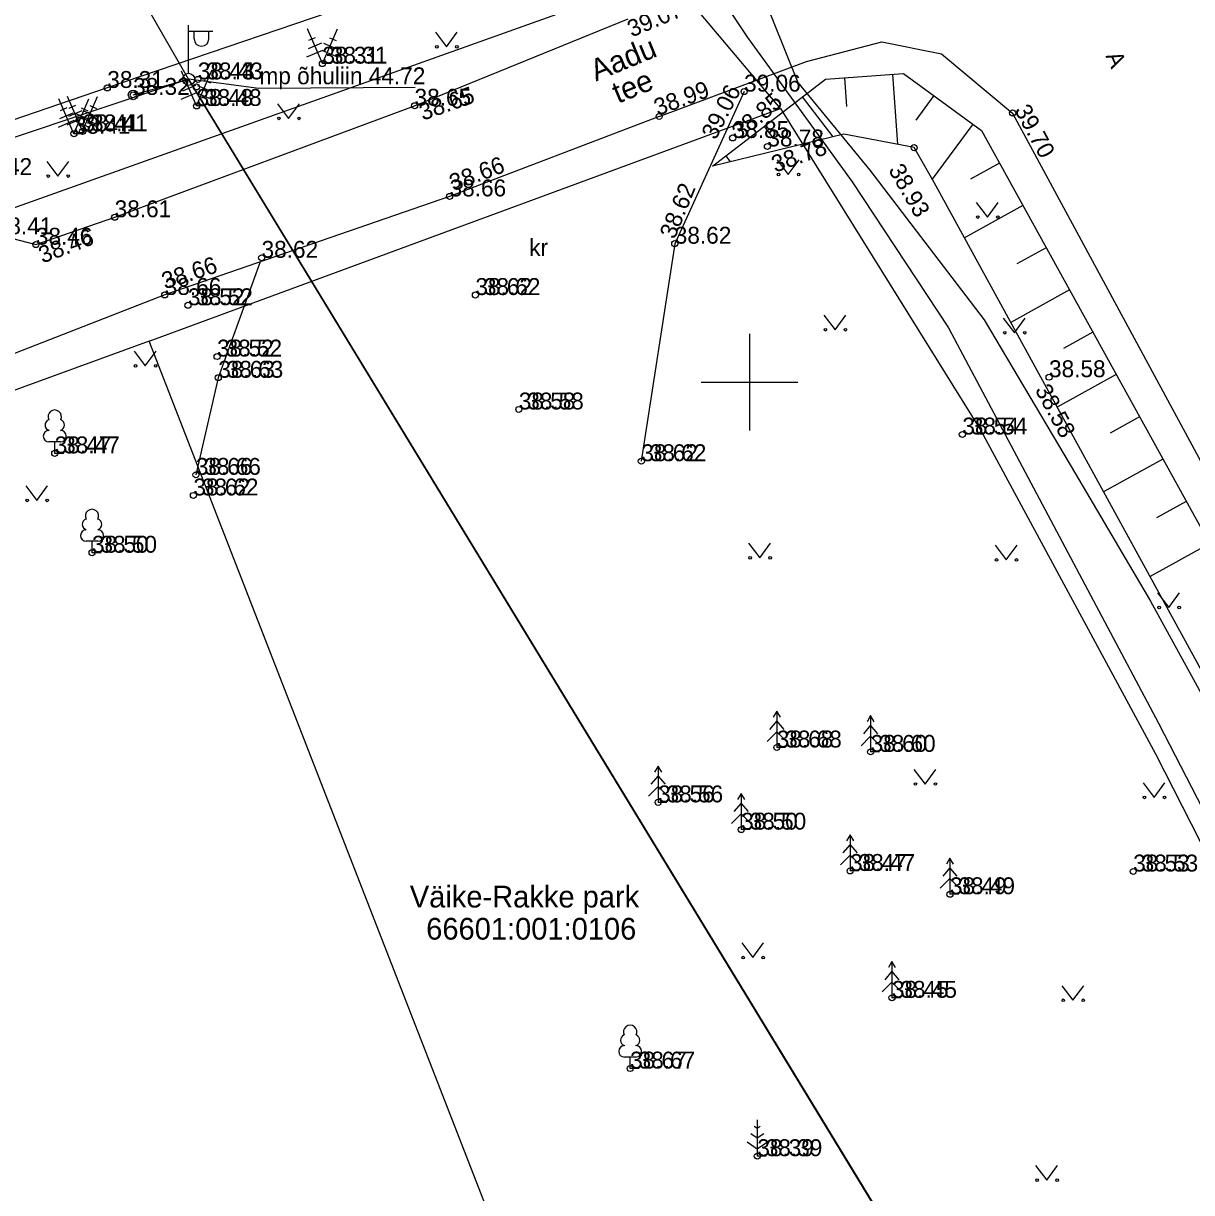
# Model space of a CAD drawing. Extents: x 627548 to 628052, y 6467984 to 6468802.
# Drawn here: x 627769.93 to 627818.31, y 6468416.43 to 6468464.86 of the extents above; entities that cross this region are included whole.
import ezdxf

# ---------------------------------------------------------------- set-up
doc = ezdxf.new("R2010")
doc.units = 0
for name, color, linetype in [('ABIJOONIS', 7, 'Continuous'), ('AED', 7, 'Continuous'), ('HALJASTUS', 7, 'Continuous'), ('KORGUS-EH2000', 7, 'Continuous'), ('MOOTKORG-EH2000', 7, 'Continuous'), ('MOOTMPUNKT', 7, 'Continuous'), ('MPOHULIIN', 7, 'Continuous'), ('PIIR', 7, 'Continuous'), ('POST', 7, 'Continuous'), ('PUU', 7, 'Continuous'), ('RELJEEF', 7, 'Continuous'), ('SIOHULIIN', 7, 'Continuous'), ('SITRASS', 7, 'Continuous'), ('TEE', 7, 'Continuous'), ('VORK', 7, 'Continuous')]:
    doc.layers.add(name, color=color, linetype=linetype)

msp = doc.modelspace()

# ---------------------------------------------------------------- linework, layer by layer
at = {"layer": 'ABIJOONIS'}
msp.add_lwpolyline([(627786.149, 6468462.211), (627779.68, 6468462.167), (627776.772, 6468462.547)], dxfattribs=at)
at = {"layer": 'AED'}
msp.add_lwpolyline([(627793.589, 6468469.234), (627785.422, 6468466.301), (627773.403, 6468462.19), (627765.44, 6468459.471)], dxfattribs=at)
at = {"layer": 'HALJASTUS'}
for p, q in [((627786.991, 6468464.496), (627787.455, 6468463.89)), ((627787.455, 6468463.89), (627787.9, 6468464.496)), ((627780.452, 6468461.538), (627780.915, 6468460.931)), ((627780.915, 6468460.931), (627781.361, 6468461.538)), ((627770.898, 6468459.148), (627771.361, 6468458.541)), ((627771.361, 6468458.541), (627771.807, 6468459.148)), ((627801.146, 6468459.215), (627801.609, 6468458.609)), ((627801.609, 6468458.609), (627802.055, 6468459.215)), ((627809.389, 6468457.45), (627809.853, 6468456.843)), ((627809.853, 6468456.843), (627810.298, 6468457.45)), ((627803.081, 6468452.783), (627803.544, 6468452.176)), ((627803.544, 6468452.176), (627803.99, 6468452.783)), ((627810.508, 6468452.659), (627810.971, 6468452.052)), ((627810.971, 6468452.052), (627811.417, 6468452.659)), ((627774.516, 6468451.29), (627774.979, 6468450.683)), ((627774.979, 6468450.683), (627775.424, 6468451.29)), ((627770.023, 6468445.714), (627770.486, 6468445.107)), ((627770.486, 6468445.107), (627770.932, 6468445.714)), ((627799.963, 6468443.33), (627800.426, 6468442.723)), ((627800.426, 6468442.723), (627800.872, 6468443.33)), ((627810.171, 6468443.244), (627810.635, 6468442.637)), ((627810.635, 6468442.637), (627811.08, 6468443.244)), ((627816.904, 6468441.278), (627817.367, 6468440.671)), ((627817.367, 6468440.671), (627817.813, 6468441.278)), ((627806.808, 6468433.963), (627807.271, 6468433.357)), ((627807.271, 6468433.357), (627807.717, 6468433.963)), ((627816.299, 6468433.41), (627816.762, 6468432.803)), ((627816.762, 6468432.803), (627817.208, 6468433.41)), ((627799.678, 6468426.772), (627800.142, 6468426.165)), ((627800.142, 6468426.165), (627800.587, 6468426.772)), ((627812.935, 6468425.003), (627813.398, 6468424.397)), ((627813.398, 6468424.397), (627813.844, 6468425.003)), ((627811.848, 6468417.554), (627812.311, 6468416.948)), ((627812.311, 6468416.948), (627812.757, 6468417.554))]:
    msp.add_line(p, q, dxfattribs=at)
for centre in [(627787.054, 6468463.89), (627787.882, 6468463.89), (627780.514, 6468460.931), (627781.343, 6468460.931), (627770.96, 6468458.541), (627771.789, 6468458.541), (627801.208, 6468458.609), (627802.037, 6468458.609), (627809.452, 6468456.843), (627810.28, 6468456.843), (627803.143, 6468452.176), (627803.972, 6468452.176), (627810.57, 6468452.052), (627811.399, 6468452.052), (627774.578, 6468450.683), (627775.407, 6468450.683), (627770.085, 6468445.107), (627770.914, 6468445.107), (627800.025, 6468442.723), (627800.854, 6468442.723), (627810.234, 6468442.637), (627811.063, 6468442.637), (627816.966, 6468440.671), (627817.795, 6468440.671), (627806.87, 6468433.357), (627807.699, 6468433.357), (627816.361, 6468432.803), (627817.19, 6468432.803), (627799.741, 6468426.165), (627800.57, 6468426.165), (627812.997, 6468424.397), (627813.826, 6468424.397), (627811.91, 6468416.948), (627812.739, 6468416.948)]:
    msp.add_circle(centre, 0.055, dxfattribs=at)
at = {"layer": 'KORGUS-EH2000'}
for centre in [(627810.9, 6468461.157), (627796.26, 6468461.007), (627806.82, 6468459.717)]:
    msp.add_circle(centre, 0.125, dxfattribs=at)
at = {"layer": 'MOOTMPUNKT'}
for centre in [(627782.313, 6468463.197), (627777.155, 6468462.545), (627773.403, 6468462.19), (627777.095, 6468462.233), (627774.474, 6468461.904), (627799.778, 6468462.039), (627777.103, 6468461.445), (627786.129, 6468461.455), (627772.022, 6468460.293), (627772.383, 6468460.393), (627799.303, 6468460.118), (627800.741, 6468459.766), (627787.58, 6468457.698), (627773.709, 6468456.834), (627770.445, 6468455.699), (627796.906, 6468455.739), (627779.793, 6468455.154), (627775.784, 6468453.617), (627788.65, 6468453.613), (627776.742, 6468453.189), (627777.951, 6468451.064), (627778, 6468450.186), (627812.406, 6468450.208), (627790.447, 6468448.872), (627808.816, 6468447.835), (627771.227, 6468447.054), (627795.521, 6468446.729), (627777.072, 6468446.164), (627776.971, 6468445.31), (627772.771, 6468442.938), (627801.131, 6468434.87), (627805.019, 6468434.689), (627796.218, 6468432.597), (627799.657, 6468431.467), (627804.168, 6468429.756), (627815.891, 6468429.733), (627808.304, 6468428.791), (627805.901, 6468424.5), (627795.058, 6468421.57), (627800.325, 6468417.941)]:
    msp.add_circle(centre, 0.125, dxfattribs=at)
at = {"layer": 'MPOHULIIN'}
msp.add_line((627808.24, 6468410.853), (627776.772, 6468462.547), dxfattribs=at)
for points in [[(627776.772, 6468462.547), (627769.965, 6468474.421)], [(627776.772, 6468462.547), (627750.093, 6468453.636)]]:
    msp.add_lwpolyline(points, dxfattribs=at)
at = {"layer": 'PIIR'}
for p, q in [((627796.61, 6468466.88), (627730.27, 6468443.22)), ((627801.28, 6468461.34), (627796.61, 6468466.88)), ((627775.14, 6468451.7), (627801.28, 6468461.34)), ((627801.28, 6468461.34), (627809.58, 6468448)), ((627775.14, 6468451.7), (627729.69, 6468435.15)), ((627802.03, 6468382.61), (627775.14, 6468451.7)), ((627809.58, 6468448), (627816.81, 6468434.6)), ((627816.81, 6468434.6), (627826.02, 6468416.53))]:
    msp.add_line(p, q, dxfattribs=at)
at = {"layer": 'POST'}
for p, q in [((627776.772, 6468462.797), (627776.772, 6468464.797)), ((627776.772, 6468464.547), (627777.772, 6468464.547)), ((627776.999, 6468464.226), (627776.999, 6468464.547)), ((627777.611, 6468464.226), (627777.611, 6468464.547))]:
    msp.add_line(p, q, dxfattribs=at)
msp.add_lwpolyline([(627774.474, 6468461.904), (627776.772, 6468462.547)], dxfattribs=at)
for centre, radius in [((627776.772, 6468462.547), 0.25), ((627776.772, 6468462.547), 0.0234), ((627774.474, 6468461.904), 0.2)]:
    msp.add_circle(centre, radius, dxfattribs=at)
msp.add_arc((627777.305, 6468464.226), 0.306, 180, 0, dxfattribs=at)
at = {"layer": 'PUU'}
for p, q in [((627782.313, 6468463.197), (627781.692, 6468464.644)), ((627782.313, 6468463.197), (627782.934, 6468464.644)), ((627782.017, 6468464.267), (627781.741, 6468464.149)), ((627782.609, 6468464.267), (627782.885, 6468464.149)), ((627782.313, 6468463.741), (627781.656, 6468463.459)), ((627782.273, 6468464.05), (627781.722, 6468463.814)), ((627782.313, 6468463.741), (627782.97, 6468463.459)), ((627782.353, 6468464.05), (627782.904, 6468463.814)), ((627782.673, 6468463.197), (627782.313, 6468463.197)), ((627777.103, 6468461.445), (627776.482, 6468462.892)), ((627777.103, 6468461.445), (627777.724, 6468462.892)), ((627777.063, 6468462.298), (627776.512, 6468462.062)), ((627776.807, 6468462.515), (627776.531, 6468462.397)), ((627777.143, 6468462.298), (627777.694, 6468462.062)), ((627777.399, 6468462.515), (627777.675, 6468462.397)), ((627772.022, 6468460.293), (627771.401, 6468461.74)), ((627772.383, 6468460.393), (627771.762, 6468461.84)), ((627772.022, 6468460.293), (627772.643, 6468461.74)), ((627772.383, 6468460.393), (627773.004, 6468461.84)), ((627777.103, 6468461.989), (627776.446, 6468461.707)), ((627777.103, 6468461.989), (627777.76, 6468461.707)), ((627771.726, 6468461.363), (627771.45, 6468461.245)), ((627772.343, 6468461.246), (627771.792, 6468461.01)), ((627772.087, 6468461.463), (627771.811, 6468461.345)), ((627772.318, 6468461.363), (627772.594, 6468461.245)), ((627772.423, 6468461.246), (627772.974, 6468461.01)), ((627772.679, 6468461.463), (627772.955, 6468461.345)), ((627777.463, 6468461.445), (627777.103, 6468461.445)), ((627772.022, 6468460.837), (627771.365, 6468460.555)), ((627771.982, 6468461.146), (627771.431, 6468460.91)), ((627772.383, 6468460.937), (627771.726, 6468460.655)), ((627772.022, 6468460.837), (627772.679, 6468460.555)), ((627772.062, 6468461.146), (627772.613, 6468460.91)), ((627772.383, 6468460.937), (627773.04, 6468460.655)), ((627772.382, 6468460.293), (627772.022, 6468460.293)), ((627772.743, 6468460.393), (627772.383, 6468460.393)), ((627771.467, 6468447.529), (627770.987, 6468447.529)), ((627771.227, 6468447.054), (627771.227, 6468447.529)), ((627771.607, 6468447.054), (627771.227, 6468447.054)), ((627773.011, 6468443.413), (627772.531, 6468443.413)), ((627772.771, 6468442.938), (627772.771, 6468443.413)), ((627773.151, 6468442.938), (627772.771, 6468442.938)), ((627801.131, 6468436.37), (627800.981, 6468436.12)), ((627801.281, 6468436.12), (627801.131, 6468436.37)), ((627801.131, 6468436.37), (627801.131, 6468434.87)), ((627805.019, 6468436.189), (627804.869, 6468435.939)), ((627805.169, 6468435.939), (627805.019, 6468436.189)), ((627805.019, 6468436.189), (627805.019, 6468434.689)), ((627801.131, 6468435.97), (627800.831, 6468435.62)), ((627801.431, 6468435.62), (627801.131, 6468435.97)), ((627805.019, 6468435.789), (627804.719, 6468435.439)), ((627805.319, 6468435.439), (627805.019, 6468435.789)), ((627801.131, 6468435.52), (627800.731, 6468435.12)), ((627801.531, 6468435.12), (627801.131, 6468435.52)), ((627805.019, 6468435.339), (627804.619, 6468434.939)), ((627805.419, 6468434.939), (627805.019, 6468435.339)), ((627801.491, 6468434.87), (627801.131, 6468434.87)), ((627805.379, 6468434.689), (627805.019, 6468434.689)), ((627796.218, 6468434.097), (627796.068, 6468433.847)), ((627796.368, 6468433.847), (627796.218, 6468434.097)), ((627796.218, 6468434.097), (627796.218, 6468432.597)), ((627796.218, 6468433.697), (627795.918, 6468433.347)), ((627796.518, 6468433.347), (627796.218, 6468433.697)), ((627796.218, 6468433.247), (627795.818, 6468432.847)), ((627796.618, 6468432.847), (627796.218, 6468433.247)), ((627799.657, 6468432.967), (627799.507, 6468432.717)), ((627799.807, 6468432.717), (627799.657, 6468432.967)), ((627799.657, 6468432.967), (627799.657, 6468431.467)), ((627796.578, 6468432.597), (627796.218, 6468432.597)), ((627799.657, 6468432.567), (627799.357, 6468432.217)), ((627799.957, 6468432.217), (627799.657, 6468432.567)), ((627799.657, 6468432.117), (627799.257, 6468431.717)), ((627800.057, 6468431.717), (627799.657, 6468432.117)), ((627800.017, 6468431.467), (627799.657, 6468431.467)), ((627804.168, 6468431.256), (627804.018, 6468431.006)), ((627804.318, 6468431.006), (627804.168, 6468431.256)), ((627804.168, 6468431.256), (627804.168, 6468429.756)), ((627804.168, 6468430.856), (627803.868, 6468430.506)), ((627804.468, 6468430.506), (627804.168, 6468430.856)), ((627804.168, 6468430.406), (627803.768, 6468430.006)), ((627804.568, 6468430.006), (627804.168, 6468430.406)), ((627808.304, 6468430.291), (627808.154, 6468430.041)), ((627808.454, 6468430.041), (627808.304, 6468430.291)), ((627808.304, 6468430.291), (627808.304, 6468428.791)), ((627804.528, 6468429.756), (627804.168, 6468429.756)), ((627808.304, 6468429.891), (627808.004, 6468429.541)), ((627808.604, 6468429.541), (627808.304, 6468429.891)), ((627808.304, 6468429.441), (627807.904, 6468429.041)), ((627808.704, 6468429.041), (627808.304, 6468429.441)), ((627808.664, 6468428.791), (627808.304, 6468428.791)), ((627805.901, 6468426), (627805.751, 6468425.75)), ((627806.051, 6468425.75), (627805.901, 6468426)), ((627805.901, 6468426), (627805.901, 6468424.5)), ((627805.901, 6468425.6), (627805.601, 6468425.25)), ((627806.201, 6468425.25), (627805.901, 6468425.6)), ((627805.901, 6468425.15), (627805.501, 6468424.75)), ((627806.301, 6468424.75), (627805.901, 6468425.15)), ((627806.261, 6468424.5), (627805.901, 6468424.5)), ((627795.298, 6468422.045), (627794.818, 6468422.045)), ((627795.058, 6468421.57), (627795.058, 6468422.045)), ((627795.438, 6468421.57), (627795.058, 6468421.57)), ((627800.325, 6468419.091), (627800.201, 6468419.174)), ((627800.325, 6468419.441), (627800.325, 6468417.941)), ((627800.449, 6468419.174), (627800.325, 6468419.091)), ((627800.325, 6468418.691), (627800.058, 6468418.869)), ((627800.592, 6468418.869), (627800.325, 6468418.691)), ((627799.901, 6468418.53), (627800.325, 6468418.248)), ((627800.325, 6468418.248), (627800.749, 6468418.53)), ((627800.685, 6468417.941), (627800.325, 6468417.941))]:
    msp.add_line(p, q, dxfattribs=at)
for centre, radius, start, end in [((627771.227, 6468448.574), 0.277, 332.5799, 207.4201), ((627771.057, 6468448.227), 0.233, 109.0217, 253.1415), ((627771.397, 6468448.227), 0.233, 286.8508, 70.9859), ((627770.99, 6468447.766), 0.238, 90.0016, 269.3953), ((627771.464, 6468447.766), 0.238, 270.6047, 89.9984), ((627772.601, 6468444.111), 0.233, 109.0217, 253.1415), ((627772.771, 6468444.458), 0.277, 332.5799, 207.4201), ((627772.941, 6468444.111), 0.233, 286.8508, 70.9859), ((627772.534, 6468443.65), 0.238, 90.0016, 269.3953), ((627773.008, 6468443.65), 0.238, 270.6047, 89.9984), ((627794.888, 6468422.743), 0.233, 109.0217, 253.1415), ((627795.058, 6468423.09), 0.277, 332.5799, 207.4201), ((627795.228, 6468422.743), 0.233, 286.8508, 70.9859), ((627794.821, 6468422.282), 0.238, 90.0016, 269.3953), ((627795.295, 6468422.282), 0.238, 270.6047, 89.9984)]:
    msp.add_arc(centre, radius, start, end, dxfattribs=at)
at = {"layer": 'RELJEEF'}
for p, q in [((627805.93, 6468462.755), (627806.136, 6468459.848)), ((627803.935, 6468462.614), (627804.02, 6468461.423)), ((627802.189, 6468461.817), (627803.459, 6468460.164)), ((627807.631, 6468461.876), (627806.889, 6468460.861)), ((627800.603, 6468460.598), (627800.968, 6468460.124)), ((627809.245, 6468460.695), (627807.573, 6468458.409)), ((627799.017, 6468459.38), (627799.206, 6468459.134)), ((627810.359, 6468459.073), (627809.151, 6468458.406)), ((627811.326, 6468457.322), (627808.904, 6468455.985)), ((627812.292, 6468455.572), (627811.078, 6468454.901)), ((627813.259, 6468453.821), (627810.825, 6468452.477)), ((627814.226, 6468452.07), (627813.006, 6468451.396)), ((627815.192, 6468450.319), (627812.747, 6468448.969)), ((627816.159, 6468448.568), (627814.933, 6468447.891)), ((627817.126, 6468446.817), (627814.668, 6468445.46)), ((627818.092, 6468445.066), (627816.861, 6468444.386)), ((627819.059, 6468443.315), (627816.59, 6468441.952))]:
    msp.add_line(p, q, dxfattribs=at)
for points in [[(627798.462, 6468458.953), (627803.154, 6468462.558), (627806.385, 6468462.787), (627809.612, 6468460.426), (627831.39, 6468420.981), (627849.758, 6468382.754), (627863.845, 6468351.725), (627866.293, 6468345.533)], [(627863.023, 6468347.157), (627861.127, 6468351.404), (627847.089, 6468382.059), (627829.031, 6468419.236), (627807.647, 6468458.279), (627806.821, 6468459.718), (627803.902, 6468460.271), (627798.462, 6468458.953)]]:
    msp.add_lwpolyline(points, dxfattribs=at)
at = {"layer": 'SIOHULIIN'}
for points in [[(627776.772, 6468462.547), (627750.093, 6468453.636)], [(627776.772, 6468462.547), (627808.24, 6468410.853)]]:
    msp.add_lwpolyline(points, dxfattribs=at)
at = {"layer": 'SITRASS'}
for points in [[(627757.217, 6468532.631), (627766.085, 6468521.026), (627772.396, 6468510.946), (627774.395, 6468507.251), (627778.965, 6468498.694), (627784.571, 6468489.044), (627791.177, 6468479.022), (627796.223, 6468473.32), (627799.931, 6468467.58), (627802.003, 6468462.412), (627804.987, 6468458.791), (627809.717, 6468452.583), (627813.499, 6468446.21), (627816.609, 6468440.925), (627819.703, 6468435.299), (627820.118, 6468434.673)], [(627757.269, 6468529.067), (627768.1, 6468513.354), (627774.946, 6468502.943), (627783.7, 6468488.286), (627791.516, 6468476.471), (627794.222, 6468472.86), (627799.922, 6468464.28), (627804.258, 6468458.3), (627808.24, 6468452.254), (627816.937, 6468435.872), (627827.445, 6468415.491), (627836.355, 6468397.304), (627844.956, 6468379.511), (627852.286, 6468362.282), (627856.189, 6468352.574), (627857.741, 6468350.531), (627858.742, 6468350.866)]]:
    msp.add_lwpolyline(points, dxfattribs=at)
at = {"layer": 'TEE'}
for points in [[(627765.165, 6468459.007), (627766.223, 6468457.303), (627768.784, 6468456.128), (627770.445, 6468455.699), (627773.709, 6468456.834), (627786.129, 6468461.455), (627794.971, 6468465.055)], [(627796.263, 6468461.011), (627802.362, 6468463.279), (627805.478, 6468464.096), (627807.948, 6468463.607), (627810.898, 6468461.152), (627832.359, 6468421.429), (627850.995, 6468383.192), (627865.917, 6468348.418)], [(627799.778, 6468462.039), (627796.906, 6468455.739), (627795.521, 6468446.729)], [(627796.263, 6468461.011), (627787.58, 6468457.698), (627775.784, 6468453.617), (627755.708, 6468445.797), (627743.362, 6468441.806), (627728.433, 6468436.983), (627717.465, 6468433.665), (627699.12, 6468428.233), (627696.098, 6468427.452), (627683.485, 6468423.1), (627674.185, 6468419.981), (627673.482, 6468419.039), (627673.355, 6468417.806)], [(627779.731, 6468454.983), (627778, 6468450.186), (627777.072, 6468446.164)]]:
    msp.add_lwpolyline(points, dxfattribs=at)
at = {"layer": 'VORK'}
for p, q in [((627800, 6468452), (627800, 6468448)), ((627798, 6468450), (627802, 6468450))]:
    msp.add_line(p, q, dxfattribs=at)

# ---------------------------------------------------------------- texts
at = {"layer": 'ABIJOONIS'}
msp.add_text('mp õhuliin 44.72', height=0.7, dxfattribs=at).set_placement((627779.707, 6468462.343))
at = {"layer": 'KORGUS-EH2000'}
for s, rotation, p in [(' 39.07', 22.7456, (627794.887, 6468464.179)), ('38.65', 19.5762, (627786.473, 6468460.829)), (' 38.99', 20.3984, (627795.962, 6468460.939)), ('39.06', 62.977, (627798.6, 6468460.005)), ('38.85', 40.2999, (627799.639, 6468460.007)), (' 39.70', 298.3809, (627810.833, 6468461.504)), ('38.78', 19.9158, (627801.066, 6468458.677)), ('38.66', 20.4877, (627787.73, 6468457.905)), (' 38.93', 299.8562, (627805.607, 6468459.021)), ('38.62', 67.7949, (627796.9, 6468455.892)), ('38.46', 20.5618, (627770.719, 6468454.915)), ('38.66', 18.0281, (627775.794, 6468453.841)), ('38.58', 298.3103, (627811.807, 6468449.688))]:
    msp.add_text(s, height=0.7, rotation=rotation, dxfattribs=at).set_placement(p)
for s, p in [('38.31', (627782.663, 6468463.197)), ('38.43', (627777.505, 6468462.545)), ('38.48', (627777.453, 6468461.445)), ('38.41', (627772.733, 6468460.393)), ('38.42', (627767.947, 6468458.583)), ('38.62', (627789, 6468453.613)), ('38.52', (627777.092, 6468453.189)), ('38.52', (627778.301, 6468451.064)), ('38.63', (627778.35, 6468450.186)), ('38.58', (627790.797, 6468448.872)), ('38.54', (627809.166, 6468447.835)), ('38.47', (627771.577, 6468447.054)), ('38.62', (627795.871, 6468446.729)), ('38.66', (627777.422, 6468446.164)), ('38.62', (627777.321, 6468445.31)), ('38.50', (627773.121, 6468442.938)), ('38.68', (627801.481, 6468434.87)), ('38.60', (627805.369, 6468434.689)), ('38.56', (627796.568, 6468432.597)), ('38.50', (627800.007, 6468431.467)), ('38.47', (627804.518, 6468429.756)), ('38.53', (627816.241, 6468429.733)), ('38.49', (627808.654, 6468428.791)), ('38.45', (627806.251, 6468424.5)), ('38.67', (627795.408, 6468421.57)), ('38.39', (627800.675, 6468417.941))]:
    msp.add_text(s, height=0.7, dxfattribs=at).set_placement(p)
at = {"layer": 'MOOTKORG-EH2000'}
for s, p in [('38.31', (627782.313, 6468463.197)), ('38.44', (627777.152, 6468462.545)), ('38.43', (627777.155, 6468462.545)), ('38.31', (627773.403, 6468462.19)), ('39.06', (627799.778, 6468462.039)), ('38.32', (627774.474, 6468461.904)), ('38.48', (627777.103, 6468461.445)), ('38.65', (627786.129, 6468461.455)), ('38.41', (627772.022, 6468460.293)), ('38.41', (627772.383, 6468460.393)), ('38.85', (627799.303, 6468460.118)), ('38.78', (627800.741, 6468459.766)), ('38.66', (627787.58, 6468457.698)), ('38.61', (627773.709, 6468456.834)), ('38.41', (627768.784, 6468456.128)), ('38.46', (627770.445, 6468455.699)), ('38.62', (627796.906, 6468455.739)), ('38.62', (627779.793, 6468455.154)), ('38.66', (627775.784, 6468453.617)), ('38.62', (627788.65, 6468453.613)), ('38.52', (627776.742, 6468453.189)), ('38.52', (627777.951, 6468451.064)), ('38.63', (627778, 6468450.186)), ('38.58', (627812.406, 6468450.208)), ('38.58', (627790.447, 6468448.872)), ('38.54', (627808.816, 6468447.835)), ('38.47', (627771.227, 6468447.054)), ('38.62', (627795.521, 6468446.729)), ('38.66', (627777.072, 6468446.164)), ('38.62', (627776.971, 6468445.31)), ('38.50', (627772.771, 6468442.938)), ('38.68', (627801.131, 6468434.87)), ('38.60', (627805.019, 6468434.689)), ('38.56', (627796.218, 6468432.597)), ('38.50', (627799.657, 6468431.467)), ('38.47', (627804.168, 6468429.756)), ('38.53', (627815.891, 6468429.733)), ('38.49', (627808.304, 6468428.791)), ('38.45', (627805.901, 6468424.5)), ('38.67', (627795.058, 6468421.57)), ('38.39', (627800.325, 6468417.941))]:
    msp.add_text(s, height=0.7, dxfattribs=at).set_placement(p)
at = {"layer": 'PIIR'}
for s, p in [('Väike-Rakke park', (627785.933, 6468428.242)), ('66601:001:0106', (627786.612, 6468426.911))]:
    msp.add_text(s, height=0.9, dxfattribs=at).set_placement(p)
at = {"layer": 'TEE'}
for s, height, rotation, p in [('Aadu', 0.9, 22.3529, (627793.638, 6468462.452)), ('A', 0.7, 294.1531, (627814.738, 6468463.518)), ('tee', 0.9, 22.3529, (627794.553, 6468461.53))]:
    msp.add_text(s, height=height, rotation=rotation, dxfattribs=at).set_placement(p)
msp.add_text('kr', height=0.7, dxfattribs=at).set_placement((627790.879, 6468455.232))

doc.saveas('drawing.dxf')
